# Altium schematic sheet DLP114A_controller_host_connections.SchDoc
size A2; Date: Not shown in title block; ApprovedBy: Not shown in title block; CheckedBy: Not shown in title block; Author: Not shown in title block; CompanyName: Not shown in title block; Engineer: Not shown in title block; Organization: Not shown in title block; Address1: Not shown in title block; Address2: Not shown in title block; Address3: Not shown in title block; Address4: Not shown in title block; DocumentNumber: 6; Revision: Use project parameter SCH_Rev; SheetNumber: 6; SheetTotal: 7; PageSetup: Record=PageOptions¦CenterHorizontal=True¦CenterVertical=True¦PrintScale=0.69¦XCorrection=1.00¦YCorrection=1.00¦PrintKind=0¦BorderSize=5000000¦LeftOffset=0¦BottomOffset=0¦Orientation=2¦PaperLength=1000¦PaperWidth=1000¦Scale=100¦PaperSource=15¦PrintQuality=600¦MediaType=1¦DitherType=10¦PaperKind=Letter¦PrintScaleMode=1
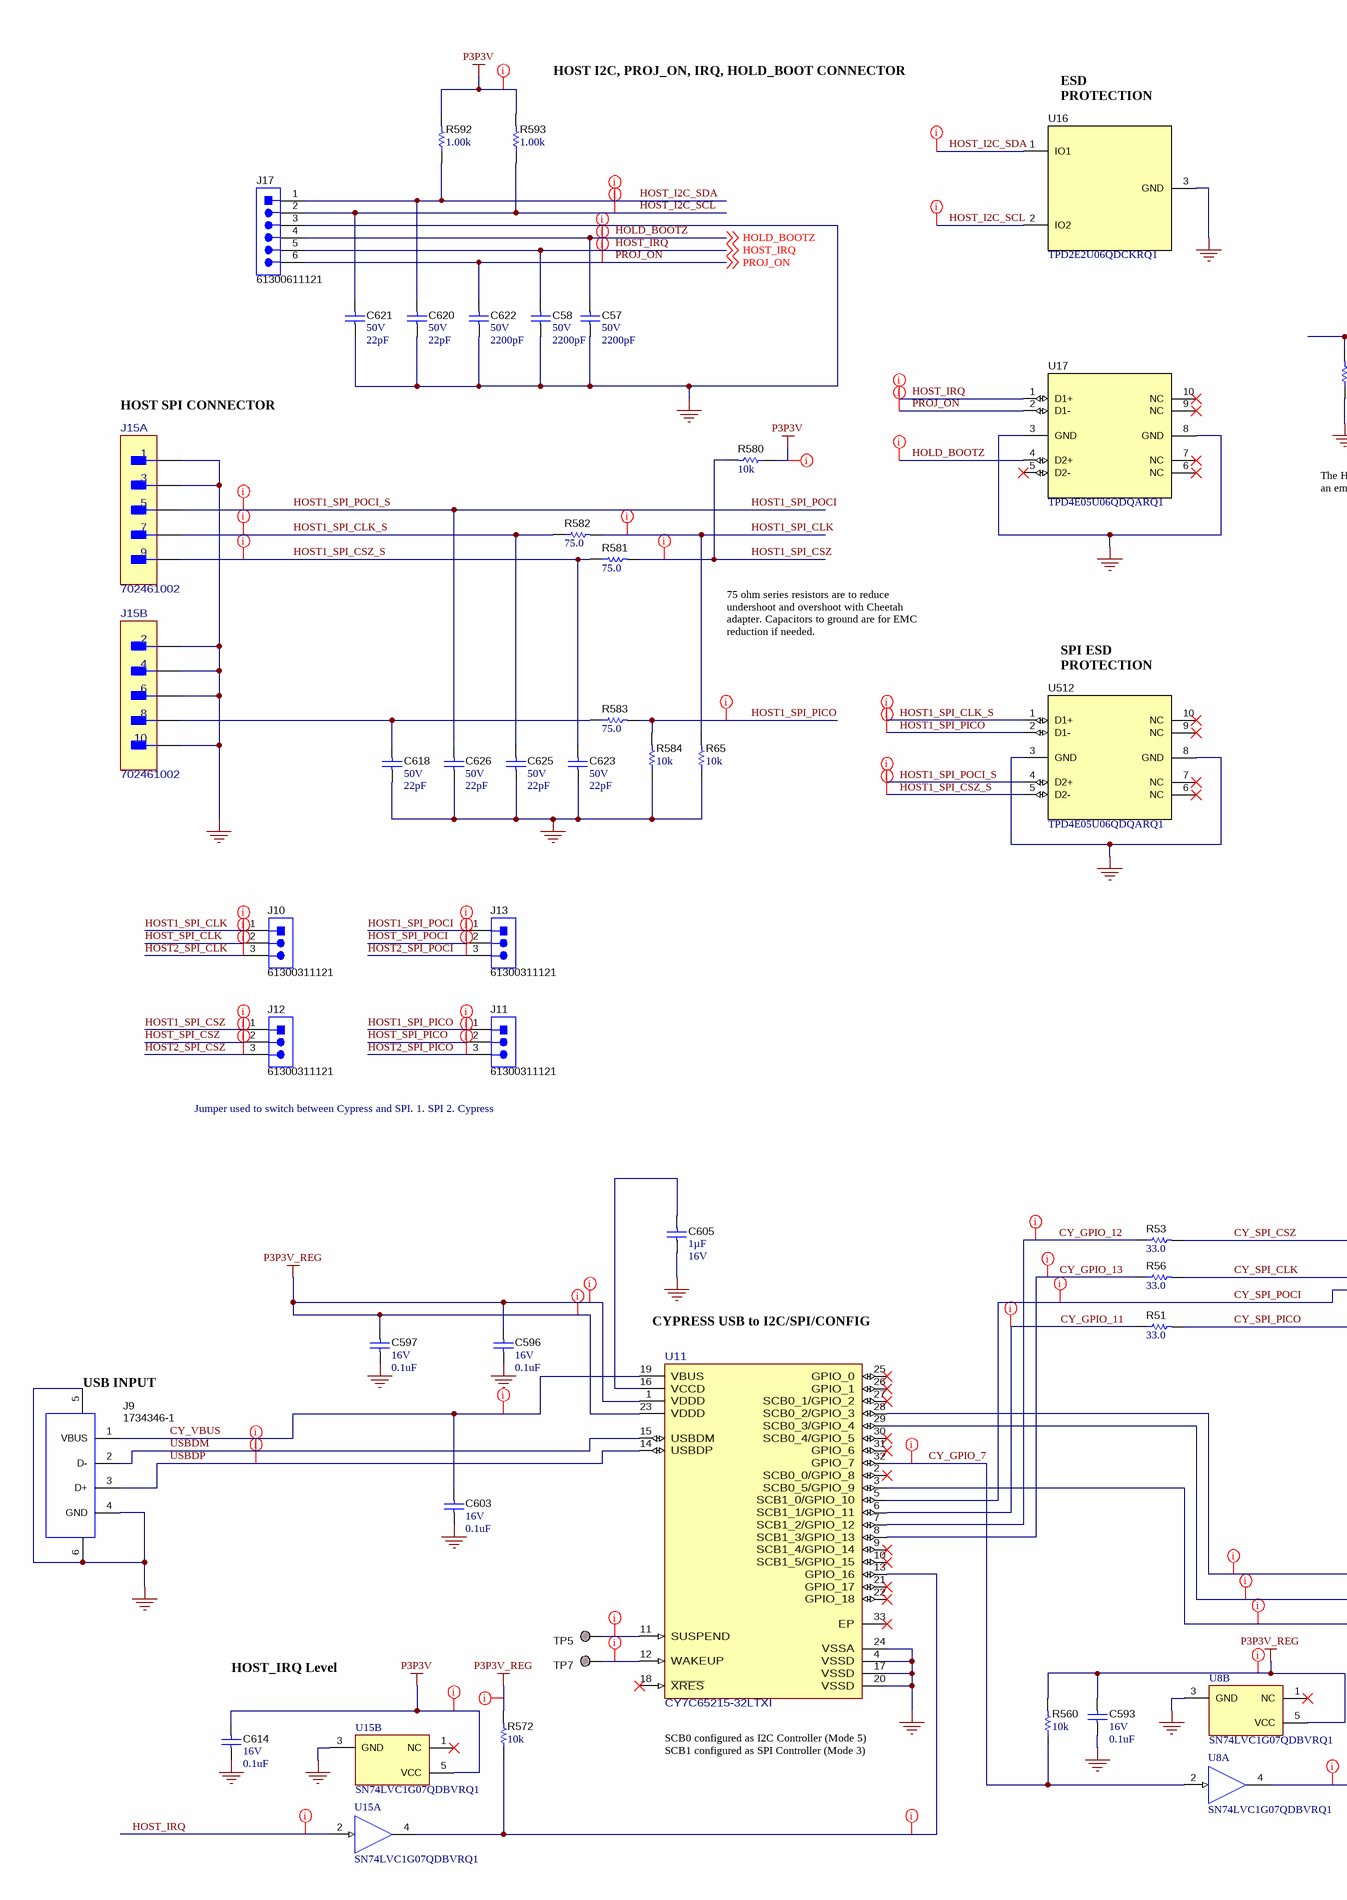
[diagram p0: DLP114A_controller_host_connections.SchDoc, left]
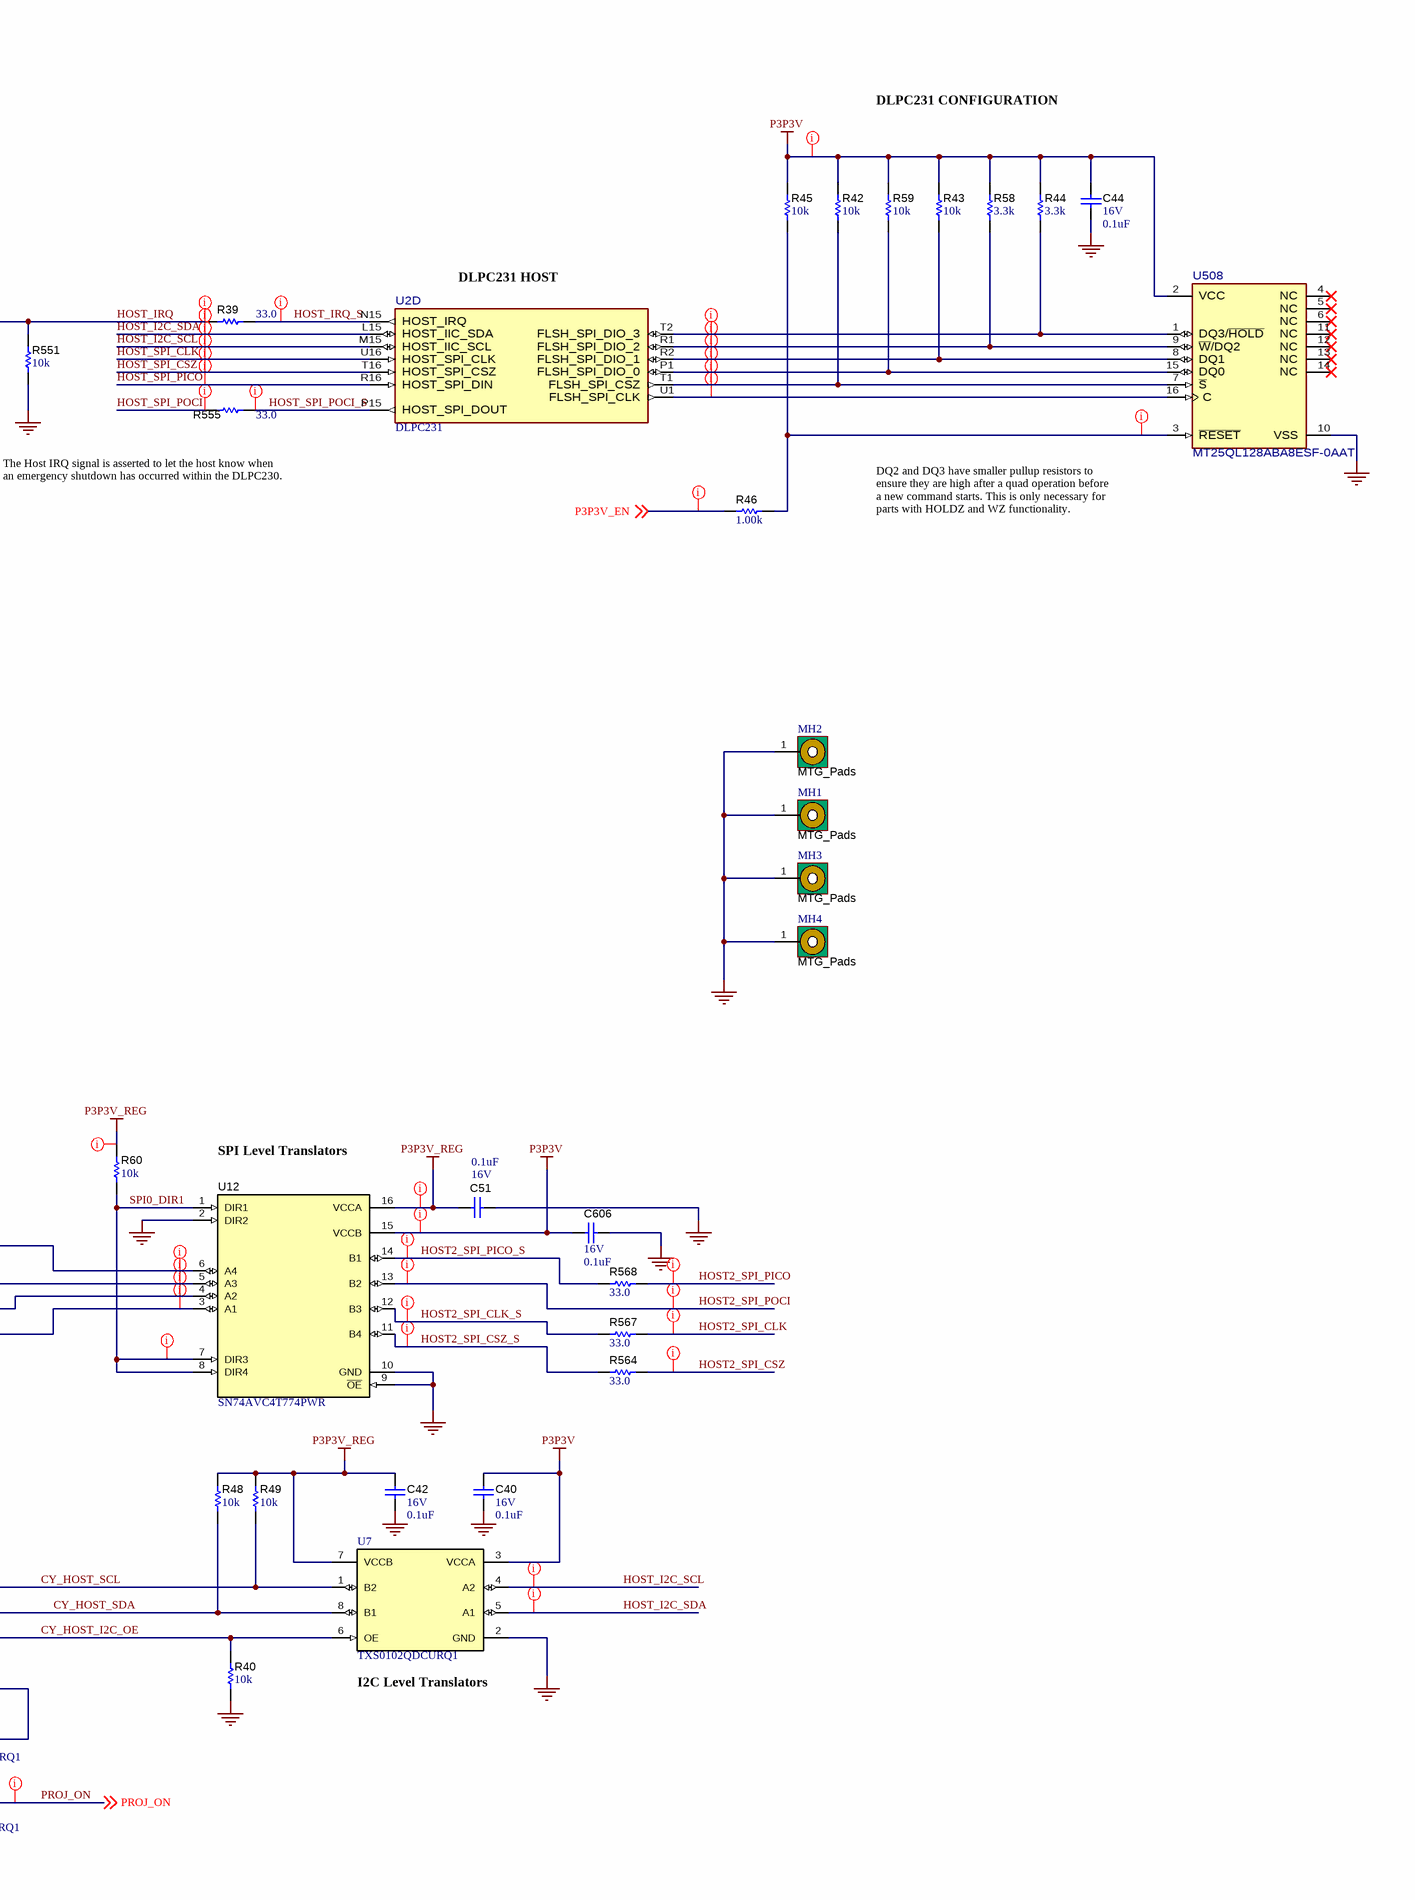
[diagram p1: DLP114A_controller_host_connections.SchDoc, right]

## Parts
C40  VDC_V: 16V  ValueDisplayed: 0.1uF  [0402]  (hidden comment: GCM155R71C104KA55D)
C42  VDC_V: 16V  ValueDisplayed: 0.1uF  [0402]  (hidden comment: GCM155R71C104KA55D)
C44  VDC_V: 16V  ValueDisplayed: 0.1uF  [0402]  (hidden comment: GCM155R71C104KA55D)
C51  VDC_V: 16V  ValueDisplayed: 0.1uF  [0402]  (hidden comment: GCM155R71C104KA55D)
C57  VDC_V: 50V  ValueDisplayed: 2200pF  [0402]  (hidden comment: CGA2B2X7R1H222K050BA)
C58  VDC_V: 50V  ValueDisplayed: 2200pF  [0402]  (hidden comment: CGA2B2X7R1H222K050BA)
C593  VDC_V: 16V  ValueDisplayed: 0.1uF  [0402]  (hidden comment: GCM155R71C104KA55D)
C596  VDC_V: 16V  ValueDisplayed: 0.1uF  [0402]  (hidden comment: GCM155R71C104KA55D)
C597  VDC_V: 16V  ValueDisplayed: 0.1uF  [0402]  (hidden comment: GCM155R71C104KA55D)
C603  VDC_V: 16V  ValueDisplayed: 0.1uF  [0402]  (hidden comment: GCM155R71C104KA55D)
C605  Cap_F: 1µF  VDC_V: 16V  [0603]  (hidden comment: GCM188R71C105KA64D)
C606  VDC_V: 16V  ValueDisplayed: 0.1uF  [0402]  (hidden comment: GCM155R71C104KA55D)
C614  VDC_V: 16V  ValueDisplayed: 0.1uF  [0402]  (hidden comment: GCM155R71C104KA55D)
C618  VDC_V: 50V  ValueDisplayed: 22pF  [0402]  (hidden comment: CL05C220JB5NNNC)
C620  VDC_V: 50V  ValueDisplayed: 22pF  [0402]  (hidden comment: CL05C220JB5NNNC)
C621  VDC_V: 50V  ValueDisplayed: 22pF  [0402]  (hidden comment: CL05C220JB5NNNC)
C622  VDC_V: 50V  ValueDisplayed: 2200pF  [0402]  (hidden comment: CGA2B2X7R1H222K050BA)
C623  VDC_V: 50V  ValueDisplayed: 22pF  [0402]  (hidden comment: CL05C220JB5NNNC)
C625  VDC_V: 50V  ValueDisplayed: 22pF  [0402]  (hidden comment: CL05C220JB5NNNC)
C626  VDC_V: 50V  ValueDisplayed: 22pF  [0402]  (hidden comment: CL05C220JB5NNNC)
J9  1734346-1  [CONN_USB-1734346]
J10  61300311121  [WURTH_61300311121]
J11  61300311121  [WURTH_61300311121]
J12  61300311121  [WURTH_61300311121]
J13  61300311121  [WURTH_61300311121]
J15  702461002  [FP-702461002_HDR10-MFG]  (parts A,B of 2)
J17  61300611121  [WURTH_61300611121]
MH1  MTG_Pads  [MTGP_252mil_157mil_6Via]  (no BOM)
MH2  MTG_Pads  [MTGP_252mil_157mil_6Via]  (no BOM)
MH3  MTG_Pads  [MTGP_252mil_157mil_6Via]  (no BOM)
MH4  MTG_Pads  [MTGP_252mil_157mil_6Via]  (no BOM)
R39  ValueDisplayed: 33.0  [0402]  (hidden comment: ERJ-2RKF33R0X)
R40  ValueDisplayed: 10k  [0402]  (hidden comment: ERJ-2GEJ103X)
R42  ValueDisplayed: 10k  [0402]  (hidden comment: ERJ-2GEJ103X)
R43  ValueDisplayed: 10k  [0402]  (hidden comment: ERJ-2GEJ103X)
R44  ValueDisplayed: 3.3k  [0402]  (hidden comment: CRCW04023K30JNED)
R45  ValueDisplayed: 10k  [0402]  (hidden comment: ERJ-2GEJ103X)
R46  ValueDisplayed: 1.00k  [0402]  (hidden comment: CRCW04021K00FKED)
R48  ValueDisplayed: 10k  [0402]  (hidden comment: ERJ-2GEJ103X)
R49  ValueDisplayed: 10k  [0402]  (hidden comment: ERJ-2GEJ103X)
R51  ValueDisplayed: 33.0  [0402]  (hidden comment: ERJ-2RKF33R0X)
R53  ValueDisplayed: 33.0  [0402]  (hidden comment: ERJ-2RKF33R0X)
R56  ValueDisplayed: 33.0  [0402]  (hidden comment: ERJ-2RKF33R0X)
R58  ValueDisplayed: 3.3k  [0402]  (hidden comment: CRCW04023K30JNED)
R59  ValueDisplayed: 10k  [0402]  (hidden comment: ERJ-2GEJ103X)
R60  ValueDisplayed: 10k  [0402]  (hidden comment: ERJ-2GEJ103X)
R65  ValueDisplayed: 10k  [0402]  (hidden comment: ERJ-2GEJ103X)
R551  ValueDisplayed: 10k  [0402]  (hidden comment: ERJ-2GEJ103X)
R555  ValueDisplayed: 33.0  [0402]  (hidden comment: ERJ-2RKF33R0X)
R560  ValueDisplayed: 10k  [0402]  (hidden comment: ERJ-2GEJ103X)
R564  ValueDisplayed: 33.0  [0402]  (hidden comment: ERJ-2RKF33R0X)
R567  ValueDisplayed: 33.0  [0402]  (hidden comment: ERJ-2RKF33R0X)
R568  ValueDisplayed: 33.0  [0402]  (hidden comment: ERJ-2RKF33R0X)
R572  ValueDisplayed: 10k  [0402]  (hidden comment: ERJ-2GEJ103X)
R580  ValueDisplayed: 10k  [0402]  (hidden comment: ERJ-2GEJ103X)
R581  ValueDisplayed: 75.0  [0402]  (hidden comment: CRCW040275R0FKED)
R582  ValueDisplayed: 75.0  [0402]  (hidden comment: CRCW040275R0FKED)
R583  ValueDisplayed: 75.0  [0402]  (hidden comment: CRCW040275R0FKED)
R584  ValueDisplayed: 10k  [0402]  (hidden comment: ERJ-2GEJ103X)
R592  ValueDisplayed: 1.00k  [0402]  (hidden comment: CRCW04021K00FKED)
R593  ValueDisplayed: 1.00k  [0402]  (hidden comment: CRCW04021K00FKED)
TP5  TESTPOINT  [TESTPOINT]  (value not drawn)  (no BOM)
TP7  TESTPOINT  [TESTPOINT]  (value not drawn)  (no BOM)
U2  DLPC231  [ZEK0324A-MFG]  (part D of 9)
U7  TXS0102QDCURQ1  [DCU0008A_N]
U8  SN74LVC1G07QDBVRQ1  [DBV0005A_N]  (parts A,B of 2)
U11  CY7C65215-32LTXI  [FP-CY7C65215-32LTXI_QFN32-IPC_C]
U12  SN74AVC4T774PWR  [PW0016A_N]
U15  SN74LVC1G07QDBVRQ1  [DBV0005A_N]  (parts A,B of 2)
U16  TPD2E2U06QDCKRQ1  [DCK0003A_N]
U17  TPD4E05U06QDQARQ1  [DQA0010A]
U508  MT25QL128ABA8ESF-0AAT  [FP-MT25QL128ABA8ESF-0AAT_SOP2-16-MFG]
U512  TPD4E05U06QDQARQ1  [DQA0010A]

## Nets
 GND: C40.2 C42.2 C44.2 C51.1 C57.2 C58.2 C593.2 C596.2 C597.2 C603.2 C605.2 C606.1 C614.2 C618.2 C620.2 C621.2 C622.2 C623.2 C625.2 C626.2 J9.4(GND) J9.5(Shield) J9.6(Shield) J15.1 J15.2 J15.3 J15.4 J15.6 J15.10 J17.3 MH1.1 MH2.1 MH3.1 MH4.1 R40.1 R65.1 R551.1 R584.1 U7.2(GND) U8.3(GND) U11.4(VSSD) U11.17(VSSD) U11.20(VSSD) U11.24(VSSA) U12.2(DIR2) U12.9(~{OE}) U12.10(GND) U15.3(GND) U16.3(GND) U17.3(GND) U17.8(GND) U508.10(VSS) U512.3(GND) U512.8(GND)  [also labelled GND]
P3P3V: C40.1 C44.1 C606.2 C614.1 R42.2 R43.2 R44.2 R45.2 R58.2 R59.2 R580.1 R592.2 R593.2 U7.3(VCCA) U12.15(VCCB) U15.5(VCC) U508.2(VCC)
P3P3V_REG: C42.1 C51.2 C593.1 C596.1 C597.1 R48.2 R49.2 R60.2 R560.2 R572.2 U7.7(VCCB) U8.5(VCC) U11.1(VDDD) U11.23(VDDD) U12.16(VCCA)
CY_GPIO_7: R560.1 U8.2(A) U11.32(GPIO_7)
CY_GPIO_11: R51.1 U11.6(SCB1_1/GPIO_11)
CY_GPIO_12: R53.1 U11.7(SCB1_2/GPIO_12)
CY_GPIO_13: R56.1 U11.8(SCB1_3/GPIO_13)
CY_HOST_I2C_OE: R40.2 U7.6(OE) U11.3(SCB0_5/GPIO_9)
CY_HOST_SCL: R49.1 U7.1(B2) U11.28(SCB0_2/GPIO_3)
CY_HOST_SDA: R48.1 U7.8(B1) U11.29(SCB0_3/GPIO_4)
CY_SPI_CLK: R56.2 U12.5(A3)
CY_SPI_CSZ: R53.2 U12.6(A4)
CY_SPI_PICO: R51.2 U12.3(A1)
CY_SPI_POCI: U11.5(SCB1_0/GPIO_10) U12.4(A2)
CY_VBUS: C603.1 J9.1(VBUS) U11.19(VBUS)
HOLD_BOOTZ: C57.1 J17.4 U17.4(D2+) ; off-sheet HOLD_BOOTZ
HOST1_SPI_CLK: J10.1 R65.2 R582.2
HOST1_SPI_CLK_S: C625.1 J15.7 R582.1 U512.1(D1+)
HOST1_SPI_CSZ: J12.1 R580.2 R581.2
HOST1_SPI_CSZ_S: C623.1 J15.9 R581.1 U512.5(D2-)
HOST1_SPI_PICO: J11.1 R583.2 R584.2 U512.2(D1-)
HOST1_SPI_POCI: C626.1 J13.1 J15.5 U512.4(D2+)  [also labelled HOST1_SPI_POCI_S]
HOST2_SPI_CLK: J10.3 R567.2
HOST2_SPI_CLK_S: R567.1 U12.12(B3)
HOST2_SPI_CSZ: J12.3 R564.2
HOST2_SPI_CSZ_S: R564.1 U12.11(B4)
HOST2_SPI_PICO: J11.3 R568.2
HOST2_SPI_PICO_S: R568.1 U12.14(B1)
HOST2_SPI_POCI: J13.3 U12.13(B2)
HOST_I2C_SCL: C621.1 J17.2 R593.1 U2.M15(HOST_IIC_SCL) U7.4(A2) U16.2(IO2)
HOST_I2C_SDA: C620.1 J17.1 R592.1 U2.L15(HOST_IIC_SDA) U7.5(A1) U16.1(IO1)
HOST_IRQ: C58.1 J17.5 R39.1 R551.2 U15.2(A) U17.1(D1+) ; off-sheet HOST_IRQ
HOST_IRQ_S: R39.2 U2.N15(HOST_IRQ)
HOST_SPI_CLK: J10.2 U2.U16(HOST_SPI_CLK)
HOST_SPI_CSZ: J12.2 U2.T16(HOST_SPI_CSZ)
HOST_SPI_PICO: J11.2 U2.R16(HOST_SPI_DIN)
HOST_SPI_POCI: J13.2 R555.1
HOST_SPI_POCI_S: R555.2 U2.P15(HOST_SPI_DOUT)
P3P3V_EN: R46.2 ; off-sheet P3P3V_EN
PROJ_ON: C622.1 J17.6 U8.4(Y) U17.2(D1-) ; off-sheet PROJ_ON
SPI0_DIR1: R60.1 U12.1(DIR1) U12.7(DIR3) U12.8(DIR4)
USBDM: J9.2(D-) U11.15(USBDM)
USBDP: J9.3(D+) U11.14(USBDP)
NetC605_1: C605.1 U11.16(VCCD)
NetC618_1: C618.1 J15.8 R583.1
NetR42_1: R42.1 U2.T1(FLSH_SPI_CSZ) U508.7(~{S})
NetR43_1: R43.1 U2.R2(FLSH_SPI_DIO_1) U508.8(DQ1)
NetR44_1: R44.1 U2.T2(FLSH_SPI_DIO_3) U508.1(DQ3/~{HOLD})
NetR45_1: R45.1 R46.1 U508.3(~{RESET})
NetR58_1: R58.1 U2.R1(FLSH_SPI_DIO_2) U508.9(~{W}/DQ2)
NetR59_1: R59.1 U2.P1(FLSH_SPI_DIO_0) U508.15(DQ0)
NetR572_1: R572.1 U11.13(GPIO_16) U15.4(Y)
NetTP5_1: TP5.1 U11.11(SUSPEND)
NetTP7_1: TP7.1 U11.12(WAKEUP)
NetU2_U1: U2.U1(FLSH_SPI_CLK) U508.16(C)

Not connected (* = marked no-connect by the designer): U8 1(NC)*; U11 2(SCB0_0/GPIO_8)* 9(SCB1_4/GPIO_14)* 10(SCB1_5/GPIO_15)* 18(~{XRES})* 21(GPIO_17)* 22(GPIO_18)* 25(GPIO_0)* 26(GPIO_1)* 27(SCB0_1/GPIO_2)* 30(SCB0_4/GPIO_5)* 31(GPIO_6)* 33(EP)*; U15 1(NC)*; U17 5(D2-)* 6(NC)* 7(NC)* 9(NC)* 10(NC)*; U508 4(NC)* 5(NC)* 6(NC)* 11(NC)* 12(NC)* 13(NC)* 14(NC)*; U512 6(NC)* 7(NC)* 9(NC)* 10(NC)*

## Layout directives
net class 50OHM: CY_GPIO_7, CY_GPIO_11, CY_GPIO_12, CY_GPIO_13, CY_HOST_I2C_OE, CY_HOST_SCL, CY_HOST_SDA, CY_SPI_CLK, CY_SPI_CSZ, CY_SPI_PICO, CY_SPI_POCI, HOLD_BOOTZ, HOST1_SPI_CLK, HOST1_SPI_CLK_S, HOST1_SPI_CSZ, HOST1_SPI_CSZ_S, HOST1_SPI_PICO, HOST1_SPI_POCI, HOST2_SPI_CLK, HOST2_SPI_CLK_S, HOST2_SPI_CSZ, HOST2_SPI_CSZ_S, HOST2_SPI_PICO, HOST2_SPI_PICO_S, HOST2_SPI_POCI, HOST_I2C_SCL, HOST_I2C_SDA, HOST_IRQ, HOST_IRQ_S, HOST_SPI_CLK, HOST_SPI_CSZ, HOST_SPI_PICO, HOST_SPI_POCI, HOST_SPI_POCI_S, NetR42_1, NetR43_1, NetR44_1, NetR45_1, NetR58_1, NetR59_1, NetR572_1, NetTP5_1, NetTP7_1, NetU2_U1, P3P3V_EN, PROJ_ON
net class POWER: CY_VBUS, P3P3V, P3P3V_REG, SPI0_DIR1
net class 90OHM (USB): USBDM, USBDP

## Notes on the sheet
- HOST I2C, PROJ_ON, IRQ, HOLD_BOOT CONNECTOR
- ESD
  PROTECTION
- DLPC231 CONFIGURATION FLASH
- (near U2) DLPC231 HOST INTERFACE
- HOST SPI CONNECTOR
- (near R555) The Host IRQ signal is asserted to let the host know when
  an emergency shutdown has occurred within the DLPC230.
- DQ2 and DQ3 have smaller pullup resistors to
  ensure they are high after a quad operation before
  a new command starts. This is only necessary for
  parts with HOLDZ and WZ functionality.
- 75 ohm series resistors are to reduce
  undershoot and overshoot with Cheetah
  adapter. Capacitors to ground are for EMC
  reduction if needed.
- SPI ESD
  PROTECTION
- Jumper used to switch between Cypress and SPI. 1. SPI 2. Cypress
- SPI Level Translators
- CYPRESS USB to I2C/SPI/CONFIG
- (near J9) USB INPUT
- HOST_IRQ Level Translators
- (near U7) I2C Level Translators
- (near U11) SCB0 configured as I2C Controller (Mode 5)
  SCB1 configured as SPI Controller (Mode 3)

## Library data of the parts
C40 C42 C44 C51 C593 C596 C597 C603 C606 C614 = CMP-0006351-2: CAP, CERM, 0.1 uF, 16 V, +/- 10%, X7R, 0402; Manufacturer: MuRata; TaMin_C: -55°C; Polarized: N; SizeAreaWB_mm2: 3; Value1: Unknown; U/M: EA; Value: 0.1uF; TaMax_C: 125°C; SizeZ_mm: 0.6; SizeX_mm: 1; SizeY_mm: 0.5; Cap_F: 100nF; AEC Category: Q200
C57 C58 C622 = CMP-0006317-2: CAP, CERM, 2200 pF, 50 V, +/- 10%, X7R, AEC-Q200 Grade 1, 0402; Manufacturer: TDK; TaMin_C: -55°C; ESR_ohm: 1.07794; Polarized: N; SizeAreaWB_mm2: 3; Value1: 1.07794 ohm; U/M: EA; Value: 2200pF; TaMax_C: 125°C; SizeZ_mm: 0.6; SizeX_mm: 1; SizeY_mm: 0.5; AEC Qualified: Y; Cap_F: 2.2nF; IRMS_A: 2.64071dA; AEC Category: Q200
C605 = CMP-0007136-5: CAP, CERM, 1 uF, 16 V, +/- 10%, X7R, AEC-Q200 Grade 1, 0603; Manufacturer: MuRata; TaMin_C: -55°C; Polarized: N; SizeAreaWB_mm2: 4.68; Value1: Unknown; U/M: EA; Value: 1uF; TaMax_C: 125°C; SizeZ_mm: 1; SizeX_mm: 1.6; SizeY_mm: 0.8; SizeArea_mm2: 1.28; AEC Qualified: Y; AEC Category: Q200
C618 C620 C621 C623 C625 C626 = CMP-0085851-1: CAP, CERM, 22 pF, 50 V,+/- 5%, C0G/NP0, 0402; Manufacturer: Walsin; AEC Qualified: N; TaMax_C: 125°C; SizeX_mm: 1; Value: 22pF; SizeZ_mm: 0.6; AEC Category: Q200; TaMin_C: -55°C; SizeArea_mm2: 0.5; SizeAreaWB_mm2: 3; U/M: EA
J9 = CMP-0054924-1: Connector, Receptacle, USB TYPE B, R/A, Top Mount SMT; Manufacturer: TE Connectivity; CNHeader: FALSE; Gender: Female; CT: TRUE
J10-J13 = CMP-0054796-4: Header, 2.54 mm, 3x1, Gold, TH; Manufacturer: Wurth Elektronik; Green_REACh: Passed; CT: FALSE; CNHeader: TRUE; Green_Lifecycle: Active
J15 = CMP-0089821-1: Connector Header Through Hole 10 position 0.100" (2.54mm); Manufacturer: Molex; Voltage_V: 250V; Conn Gender: Male; SizeZ_mm: 9.47mm; Standoff Height: 0.38mm; Row_Count: 2; Conn Orientation: Vertical; AEC Qualified: No; ContactFinish: Gold,Nickel; Current_A: 2.5A
J17 = CMP-0054801-2: Header, 2.54 mm, 6x1, Gold, TH; Manufacturer: Wurth Elektronik; Cert_UL: Y; Gender: Male; Row_Count: 1; Shrouded: N; Pitch_mm: 2.54
MH1-MH4 = CMP-0078422-2: PCB Mounting Hole; Manufacturer: Any; Key: Mounting Hole (non-standard)
R39 R51 R53 R56 R555 R564 R567 R568 = CMP-0026696-1: RES, 33.0, 1%, 0.1 W, 0402; Manufacturer: Panasonic; Power_W: 100mW; TempCo: 100 ppm/C; Value_Code: 33R0; U/M: EA; Value: 33.0; Res_ohm: 33; SizeX_mm: 1; SizeY_mm: 0.5; SizeZ_mm: 0.6; Value2: 0.1W; VDC_V: 50V; AEC Category: Q200
R40 R42 R43 R45 R48 R49 R59 R60 R65 R551 R560 R572 R580 R584 = CMP-0026994-4: RES, 10 k, 5%, 0.1 W, AEC-Q200 Grade 0, 0402; Manufacturer: Panasonic; Power_W: 100mW; TempCo: 200 ppm/C; Value_Code: 10k0; U/M: EA; Value: 10k; EIA_Code: E24; SizeX_mm: 1; SizeY_mm: 0.5; SizeZ_mm: 0.6; Value2: 0.1W; AEC Qualified: Y; VDC_V: 50V; AEC Grade: 0; AEC Category: Q200
R44 R58 = CMP-0026918-5: RES, 3.3 k, 5%, 0.063 W, AEC-Q200 Grade 0, 0402; Manufacturer: Vishay-Dale; Power_W: 63mW; TempCo: 200 ppm/C; Value_Code: 3k30; Value: 3.3k; EIA_Code: E24; SizeX_mm: 1; SizeY_mm: 0.5; SizeZ_mm: 0.6; Value2: 0.063W; AEC Qualified: Y; VDC_V: 50V; AEC Category: Q200; AEC Grade: 0
R46 R592 R593 = CMP-0026071-3: RES, 1.00 k, 1%, 0.063 W, AEC-Q200 Grade 0, 0402; Manufacturer: Vishay-Dale; Power_W: 63mW; TempCo: 100 ppm/C; Value_Code: 1k00; Value: 1.00k; EIA_Code: E96; Res_ohm: 1k; SizeX_mm: 1; SizeY_mm: 0.5; SizeZ_mm: 0.6; Value2: 0.063W; AEC Qualified: Y; VDC_V: 50V; AEC Category: Q200; AEC Grade: 0
R581-R583 = CMP-0026544-2: RES, 75.0, 1%, 0.063 W, AEC-Q200 Grade 0, 0402; Manufacturer: Vishay-Dale; Power_W: 63mW; TempCo: 100 ppm/C; Value_Code: 75R0; Value: 75.0; EIA_Code: E96; Res_ohm: 75; SizeX_mm: 1; SizeY_mm: 0.5; SizeZ_mm: 0.6; Value2: 0.063W; AEC Qualified: Y; VDC_V: 50V; AEC Category: Q200; AEC Grade: 0
TP5 TP7 = CMP-0078143-2: TEST POINT.  No entry in BOM.
U2 = CMP-0096130-1: Manufacturer: Texas Instruments; Standoff Height: 0.35mm; SizeZ_mm: 1.5mm
U7 = CMP-0051205-2: Automotive 2-Bit Bidirectional Voltage-Level Translator for Open-Drain and Push-Pull Application, DCU0008A (VSSOP-8); Manufacturer: Texas Instruments; Generic Part Number: TXS0102-Q1; 3-State Output: No; Logic: True; VCC(Max)(V): 5.5; Voltage(Nom)(V): 3.3; Bits(#): 2; ICC @ Nom Voltage(Max)(mA): 0.012; Output Type: CMOS; tpd @ Nom Voltage(Max)(ns): 4.2; VCC(Min)(V): 1.65; Input Type: TTL; AEC Category: Q200; AEC Qualified: Y; CompType: IC; SizeAreaWB_mm2: 12.6; SizeArea_mm2: 6.4; SizeX_mm: 3.2; SizeY_mm: 2.0; SizeZ_mm: 0.9
U8 U15 = CMP-0051394-2: Automotive Catalog Single Buffer/Driver With Open-Drain Output, DBV0005A (SOT-23-5); Manufacturer: Texas Instruments; Generic Part Number: SN74LVC1G07-Q1; ICC @ Nom Voltage(Max)(mA): 0.01; VCC(Min)(V): 1.65; 3-State Output: No; Voltage(Nom)(V): 1.8,2.5,3.3,5; Logic: True; Input Type: CMOS/TTL; Bits(#): 1; Output Drive (IOL/IOH)(Max)(mA): 32/-32; Output Type: CMOS; VCC(Max)(V): 5.5; tpd @ Nom Voltage(Max)(ns): 9.8,7,5.7,4.9; F @ Nom Voltage(Max)(Mhz): 150; AEC Category: Q200; AEC Qualified: Y; CompType: IC; SizeAreaWB_mm2: 14.82; SizeArea_mm2: 8.12; SizeX_mm: 2.8; SizeY_mm: 2.9; SizeZ_mm: 1.45
U11 = CMP-0086752-1: USB Bridge, USB to I²C USB 2.0 UART Interface 32-QFN (5x5); Manufacturer: Cypress; SizeZ_mm: 1mm
U12 = CMP-0066451-2: 4-Bit Dual-Supply Bus Transceiver With Configurable Voltage-Level Shifting and 3-State Outputs, PW0016A (TSSOP-16); Alternate Manufacturer: Texas Instruments; CompType: IC; SizeArea_mm2: 32.0; SizeZ_mm: 1.2; SizeAreaWB_mm2: 58.8; AEC Category: Q200; AEC Qualified: N; SizeY_mm: 5.0; SizeX_mm: 6.4; Rating: Catalog
U16 = CMP-0073595-1: Automotive Dual-Channel High-Speed ESD Protection Device, DCK0003A (SOT-SC70-3); Alternate Manufacturer: Texas Instruments; SizeAreaWB_mm2: 9.3; U/M: EA; SizeZ_mm: 1.1; SizeX_mm: 2.1; SizeY_mm: 2.0; SizeArea_mm2: 4.2; CompType: IC
U17 U512 = CMP-0073599-3: Automotive 4-Channel ESD Protection Solution for SuperSpeed (up to 5 Gbps) Interface, DQA0010A (USON-10); Manufacturer: Texas Instruments; SizeZ_mm: 0.55; SizeX_mm: 1.0; SizeY_mm: 2.5; CompType: IC; SizeAreaWB_mm2: 7.0; AEC Category: Q200; AEC Qualified: Y
U508 = CMP-0086504-1: FLASH - NOR Memory IC 128Mb (16M x 8) SPI 133MHz  16-SOP2; Manufacturer: Micron; SizeZ_mm: 2.65mm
